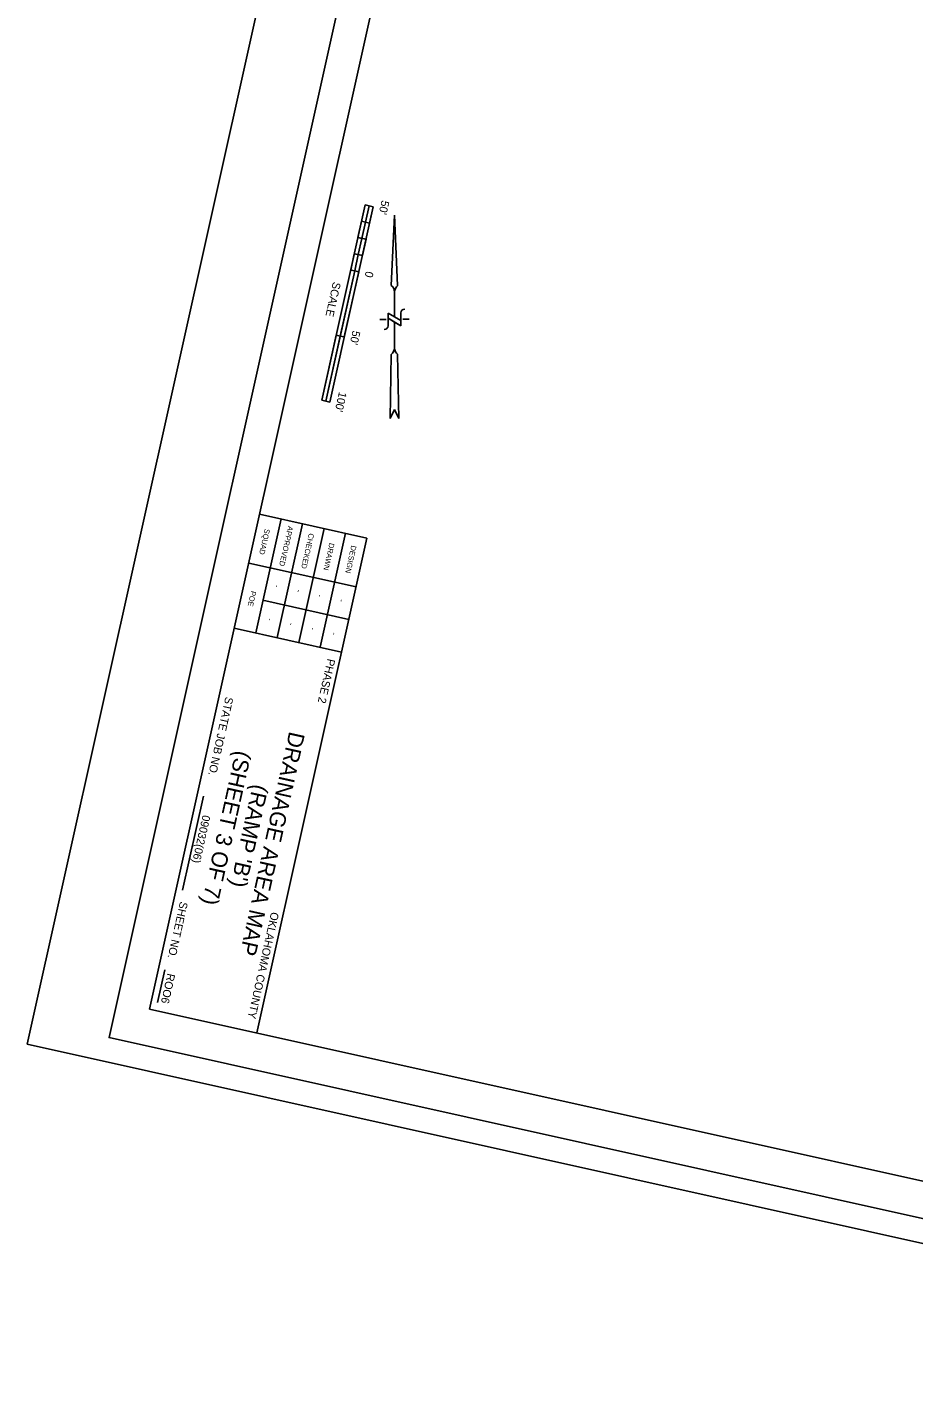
# Model space of a CAD drawing. Extents: x 2149887 to 2151449, y 143603 to 146901.
# Drawn here: x 2149887 to 2150552, y 144883 to 145906 of the extents above; entities that cross this region are included whole.
import ezdxf

# ---------------------------------------------------------------- set-up
doc = ezdxf.new("R2010")
doc.units = 0
for name, color, linetype in [('SHT_North_Arrow', 7, 'Continuous'), ('SHT_Plot_Shape_Full', 7, 'Continuous'), ('SHT_Plot_Shape_Half', 7, 'Continuous'), ('SHT_Scale', 7, 'Continuous'), ('SHT_Sheet_Border', 7, 'Continuous'), ('SHT_Standard_Sheet_Lines', 7, 'Continuous'), ('SHT_Standard_Sheet_Txt', 7, 'Continuous')]:
    doc.layers.add(name, color=color, linetype=linetype)

msp = doc.modelspace()

# ---------------------------------------------------------------- linework, layer by layer
at = {"layer": 'SHT_North_Arrow'}
for p, q in [((2150160, 145712.3), (2150162.4, 145765.2)), ((2150162.4, 145765.2), (2150160, 145712.3)), ((2150162.4, 145765.2), (2150164.8, 145712.3)), ((2150164.8, 145712.3), (2150162.4, 145765.2)), ((2150162.4, 145688.9), (2150162.4, 145707.6)), ((2150156.2, 145686.9), (2150151.4, 145686.9)), ((2150167.2, 145686), (2150157.6, 145691.7)), ((2150157.6, 145691.7), (2150167.2, 145686)), ((2150157.6, 145691.7), (2150157.6, 145682.2)), ((2150162.4, 145688.9), (2150157.6, 145691.7)), ((2150157.6, 145691.7), (2150157.6, 145687.9)), ((2150167.2, 145682.2), (2150157.6, 145687.9)), ((2150167.2, 145686), (2150162.4, 145688.9)), ((2150167.2, 145691.8), (2150167.2, 145682.2)), ((2150173.4, 145687), (2150168.7, 145687)), ((2150162.4, 145665.4), (2150162.4, 145685)), ((2150167.2, 145682.2), (2150167.2, 145686)), ((2150159.1, 145612.6), (2150160, 145660.6)), ((2150160, 145660.6), (2150159.1, 145612.6)), ((2150165.8, 145612.6), (2150164.8, 145660.6)), ((2150165.8, 145612.6), (2150164.8, 145660.6)), ((2150159.1, 145612.6), (2150162.4, 145619.3)), ((2150159.1, 145612.6), (2150162.4, 145619.3)), ((2150162.4, 145619.3), (2150165.8, 145612.6)), ((2150162.4, 145619.3), (2150165.8, 145612.6))]:
    msp.add_line(p, q, dxfattribs=at)
for points in [[(2150157.6, 145687.9), (2150162.4, 145685), (2150167.2, 145682.2)], [(2150162.4, 145665.4), (2150162.4, 145665.4), (2150162.4, 145665.4)]]:
    msp.add_lwpolyline(points, dxfattribs=at)
for centre, radius, start, end in [((2150156.7, 145707.6), 5.76, 0.0232, 54.4034), ((2150156.7, 145707.6), 5.76, 0.0232, 54.4034), ((2150168.2, 145707.6), 5.76, 125.6431, 180.0232), ((2150168.2, 145707.6), 5.76, 125.6431, 180.0232), ((2150170.1, 145691.8), 2.88, 90.0232, 180.0232), ((2150154.7, 145682.2), 2.88, 270.0232, 0.0232), ((2150154.1, 145666.5), 8.43, 314.9799, 352.4421), ((2150154.1, 145666.5), 8.43, 314.9799, 352.0822), ((2150170.8, 145666.5), 8.43, 187.6043, 225.0665), ((2150170.8, 145666.5), 8.43, 187.9642, 225.0665)]:
    msp.add_arc(centre, radius, start, end, dxfattribs=at)
at = {"layer": 'SHT_Plot_Shape_Full'}
msp.add_lwpolyline([(2151449.2, 146640.3), (2151058.5, 144883.2), (2149887.1, 145143.7), (2150277.8, 146900.7)], close=True, dxfattribs=at)
at = {"layer": 'SHT_Plot_Shape_Half'}
msp.add_lwpolyline([(2151391.2, 146569.3), (2151022.2, 144909.8), (2149948.4, 145148.6), (2150317.4, 146808.1)], close=True, dxfattribs=at)
at = {"layer": 'SHT_Scale'}
for p, q in [((2150140.4, 145772.8), (2150107.9, 145626.3)), ((2150146.5, 145771.4), (2150114, 145625)), ((2150146.5, 145771.4), (2150140.4, 145772.8)), ((2150143.5, 145772.1), (2150140.8, 145759.9)), ((2150143.5, 145772.1), (2150140.8, 145759.9)), ((2150146.5, 145771.4), (2150143.5, 145772.1)), ((2150143.8, 145759.2), (2150146.5, 145771.4)), ((2150137.7, 145760.6), (2150135, 145748.3)), ((2150143.8, 145759.2), (2150137.7, 145760.6)), ((2150140.8, 145759.9), (2150137.7, 145760.6)), ((2150140.8, 145759.9), (2150138, 145747.7)), ((2150138, 145747.7), (2150140.8, 145759.9)), ((2150140.8, 145759.9), (2150143.8, 145759.2)), ((2150141.1, 145747), (2150135, 145748.3)), ((2150141.1, 145747), (2150135, 145748.3)), ((2150135, 145748.3), (2150138, 145747.7)), ((2150138, 145747.7), (2150135.3, 145735.5)), ((2150138, 145747.7), (2150135.3, 145735.5)), ((2150141.1, 145747), (2150138, 145747.7)), ((2150138.4, 145734.8), (2150141.1, 145747)), ((2150132.3, 145736.1), (2150129.6, 145723.9)), ((2150138.4, 145734.8), (2150132.3, 145736.1)), ((2150135.3, 145735.5), (2150132.3, 145736.1)), ((2150135.3, 145735.5), (2150132.6, 145723.3)), ((2150132.6, 145723.3), (2150135.3, 145735.5)), ((2150135.3, 145735.5), (2150138.4, 145734.8)), ((2150132.6, 145723.3), (2150110.9, 145625.6)), ((2150132.6, 145723.3), (2150121.8, 145674.5)), ((2150124.8, 145673.8), (2150135.7, 145722.6)), ((2150129.6, 145723.9), (2150132.6, 145723.3)), ((2150129.6, 145723.9), (2150132.6, 145723.3)), ((2150132.6, 145723.3), (2150135.7, 145722.6)), ((2150135.7, 145722.6), (2150132.6, 145723.3)), ((2150118.7, 145675.1), (2150107.9, 145626.3)), ((2150110.9, 145625.6), (2150121.8, 145674.5)), ((2150118.7, 145675.1), (2150121.8, 145674.5)), ((2150121.8, 145674.5), (2150118.7, 145675.1)), ((2150121.8, 145674.5), (2150124.8, 145673.8)), ((2150121.8, 145674.5), (2150124.8, 145673.8)), ((2150110.9, 145625.6), (2150107.9, 145626.3)), ((2150107.9, 145626.3), (2150110.9, 145625.6)), ((2150114, 145625), (2150110.9, 145625.6))]:
    msp.add_line(p, q, dxfattribs=at)
at = {"layer": 'SHT_Sheet_Border'}
for p, q in [((2150061.2, 145541), (2150141.8, 145523)), ((2150141.8, 145523), (2150059.3, 145152.1)), ((2150042.3, 145455.5), (2150122.8, 145437.6))]:
    msp.add_line(p, q, dxfattribs=at)
msp.add_lwpolyline([(2149978.8, 145170), (2150320.6, 146707.5), (2151345.6, 146479.6), (2151003.7, 144942.1)], close=True, dxfattribs=at)
at = {"layer": 'SHT_Standard_Sheet_Lines'}
for p, q in [((2150053.1, 145504.3), (2150133.7, 145486.4)), ((2150063.8, 145476.4), (2150128.3, 145462)), ((2150019.2, 145329.5), (2150003.5, 145259.2)), ((2149990.2, 145199.5), (2149984.8, 145174.9))]:
    msp.add_line(p, q, dxfattribs=at)
for points in [[(2150058.4, 145452), (2150077.4, 145537.4)], [(2150074.5, 145448.4), (2150093.5, 145533.8)], [(2150090.6, 145444.8), (2150109.6, 145530.2)], [(2150106.7, 145441.2), (2150125.7, 145526.6)]]:
    msp.add_lwpolyline(points, dxfattribs=at)

# ---------------------------------------------------------------- texts
at = {"layer": 'SHT_Scale'}
for s, p in [("50'", (2150152.8, 145776.5)), ('0', (2150141, 145723.4)), ('SCALE', (2150116.4, 145715.4)), ("50'", (2150131.1, 145678.9)), ("100'", (2150120.9, 145633))]:
    msp.add_text(s, height=6, rotation=257.4638, dxfattribs=at).set_placement(p)
at = {"layer": 'SHT_Standard_Sheet_Txt'}
for s, height, p in [('SQUAD', 4, (2150065.2, 145530.3)), ('APPROVED', 4, (2150082.6, 145532.4)), ('CHECKED', 4, (2150098.3, 145526.9)), ('DRAWN', 4, (2150113.6, 145519.7)), ('DESIGN', 4, (2150130.1, 145517.8)), ('POE', 4, (2150054.9, 145483.7)), ('-', 4, (2150072.8, 145488.2)), ('-', 4, (2150088.9, 145484.6)), ('-', 4, (2150105, 145481)), ('-', 4, (2150121.1, 145477.4)), ('-', 4, (2150067.3, 145463.3)), ('-', 4, (2150083.4, 145459.8)), ('-', 4, (2150099.5, 145456.2)), ('-', 4, (2150115.6, 145452.6)), ('PHASE 2', 6, (2150112.2, 145433)), ('STATE JOB NO.', 6, (2150035.8, 145404.4)), ('DRAINAGE AREA MAP', 12, (2150083.6, 145378.6)), ('(SHEET 3 OF 7)', 12, (2150043.5, 145364.3)), ("(RAMP 'B')", 12, (2150056.3, 145339.1)), ('09032(06)', 6, (2150018.6, 145315.8)), ('SHEET NO. ', 6, (2150001.7, 145250.9)), ('OKLAHOMA COUNTY', 6, (2150070, 145243.1)), ('ROO6', 6, (2149992.2, 145197.1))]:
    msp.add_text(s, height=height, rotation=257.4638, dxfattribs=at).set_placement(p)

doc.saveas('drawing.dxf')
